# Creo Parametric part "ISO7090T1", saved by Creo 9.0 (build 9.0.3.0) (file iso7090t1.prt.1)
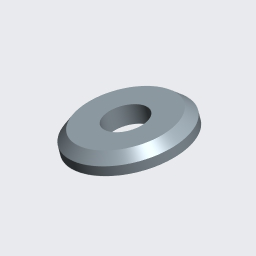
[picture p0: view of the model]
Units: millimeter Kilogram Sec (mmKs); MM, KILOGRAM, SECS

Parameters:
  BEZEICHNUNG = "DIN 125-A D"
  BENENNUNG = "Scheibe"
  INFO = "PK A; bis Haerte 250HV; fuer Sechskant"
  MATERIAL = "Stahl"

Other parameters: D2, D3, KATEGORIE

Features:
  1. chamfer

Named dimensions: Bohrungsdurchmesser, Aussendurchmesser, Dicke

Layers: KONSTRUKTIONSELEMENTE

Family table entries: ISO7090T1A1_7, ISO7090T1, value(d_val), value(s_val), DIN 125 - A 1.7, value(i_val), ISO7090T1A1_8, ISO7090T1, )DIN 125 - A 1.8, ISO7090T1A2_2, ISO7090T1, )DIN 125 - A 2.2, ISO7090T1A2_5, ISO7090T1, )DIN 125 - A 2.5, ISO7090T1A2_7, ISO7090T1, )DIN 125 - A 2.7, ISO7090T1A2_8, ISO7090T1, )DIN 125 - A 2.8, ISO7090T1A3_2, ISO7090T1, )DIN 125 - A 3.2, ISO7090T1A3_7, ISO7090T1, 2/ , )DIN 125 - A 3.7, ISO7090T1A4_3, ISO7090T1, 2/", )DIN 125 - A 4.3, )_ISO7090T1A4_3, )PRO_MP_CSYS, data(checksum_info), ISO7090T1A5_3, ISO7090T1, 2/$, )DIN 125 - A 5.3, )_ISO7090T1A5_3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

Surfaces: 4 cylinder, 2 plane, 2 cone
